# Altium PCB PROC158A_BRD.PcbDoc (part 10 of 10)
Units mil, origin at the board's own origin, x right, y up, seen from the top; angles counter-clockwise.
Board outline 3346.45 x 4921.26 mil, 8 copper layers (Top Layer, GND1, SIG1, PWR1, PWR2, SIG2, GND2, Bottom Layer), stack 54.534 mil thick; 718 components, 459 nets, 2307 pads, 1179 vias.
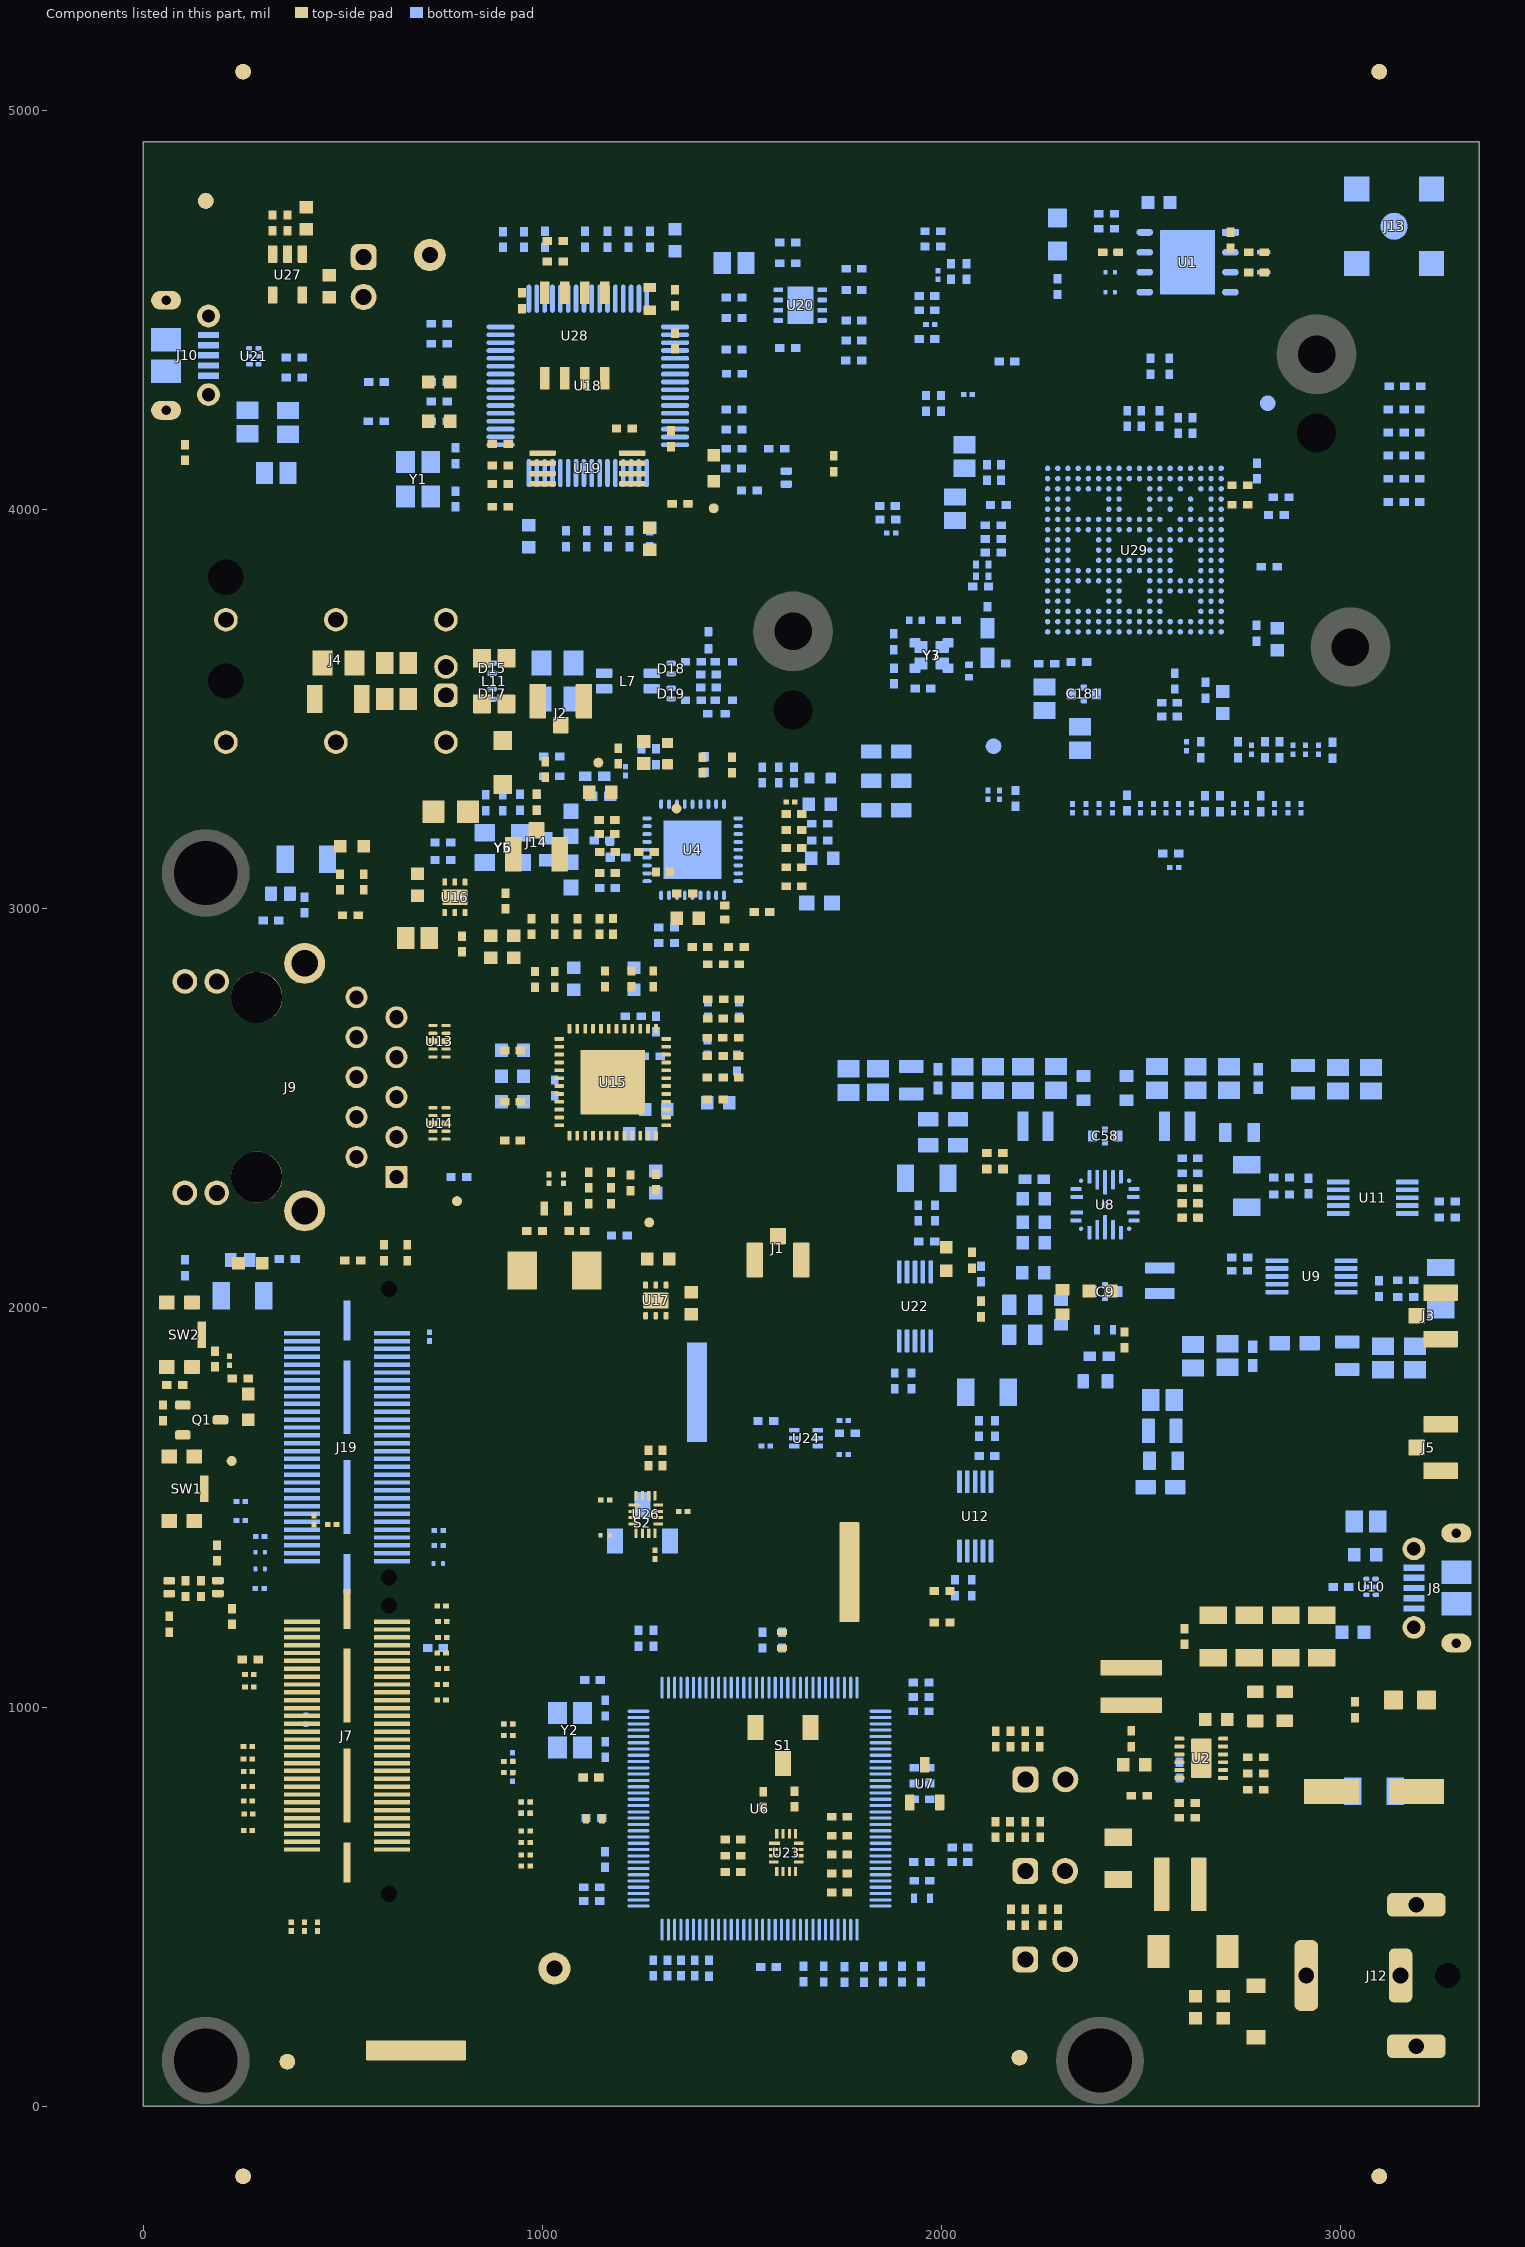
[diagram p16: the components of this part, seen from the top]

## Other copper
Top Layer:
  pour cut-out: 2380,1076 2380,1028.09 2570,1028.09 2570,1076
  pour cut-out: 473.41,3677.84 473.41,3464.33 806.94,3464.33 806.94,3677.84
  text ".Layer_Name" at 931.33,-846.68 h60
PWR1:
  pour cut-out: 2381,3395.5 2381,3394 2382.5,3392.5 2400,3392.5 2400,3395.5
  pour cut-out: 2290,3922.5 2290,3893 2289.5,3892.5 2285,3892.5 2285,3922.5
  text "PWR1" at 950,-848.19 h60
PWR2:
  text "PWR2" at 950,-848.19 h60
GND1:
  text "GND1" at 948.77,-848.19 h60
SIG1:
  text "SIG1" at 948.77,-848.19 h60
SIG2:
  text "SIG2" at 945.99,-848.19 h60
GND2:
  pour cut-out: 1914.4,3800 2011.73,3800 2022.06,3788.16 2137.22,3788.16 2137.22,3797 2032,3797 2019.99,3812 1911,3812 1840,3741 1840,3535 1868,3507 2135.9,3507 2213,3584.1 2213,3738.51 2200,3738.51 2200,3592.56 2125.41,3516.97 1871.56,3516.97 1850.89,3537.64 1850.89,3736.49
  text "GND4" at 950,-848.19 h60
Bottom Layer:
  pour cut-out: 2515,4285 2515,4228.32 2528.32,4228.32 2528.32,4284.68 2528,4285
  pour cut-out: 2820,3600 2820,3550 2885,3550 2885,3600
  pour cut-out: 2200,3432.31 2293.69,3432.31 2297,3429 2297,3417.76 2295.63,3416.39 2198.39,3416.39 2198,3416 2198,3430.31
  pour cut-out: 2187.04,3521.98 2187.04,3353.26 2189.19,3351.11 2195.52,3351.11 2200,3355.59 2200,3509.02
  pour cut-out: 2019,3876.75 2019,3812 2028,3812 2028,3876.75
  pour cut-out: 2102.11,3852.35 2027,3852.35 2027,3842.5 2102.11,3842.5
  pour cut-out: 2763,4105.53 2763,4140 2778,4155 2798,4155 2808,4145 2808,4128 2809,4127 2813,4127 2815,4129 2815,4147 2802,4160 2774,4160 2755.63,4141.63 2755.63,4106.34 2756.43,4105.53
  pour cut-out: 1980,3974.94 1980.06,3974.94 1990.06,3974.94 1990.06,3885.06 1990,3885 1980,3885 1980,3970
  pour cut-out: 1958,4205 2019,4205 2030,4216 2030,4287.4 2040,4287.4 2040,4211 2024,4195 1958,4195
  pour cut-out: 2480,4285 2480,4225 2485,4225 2485,4285
  pour cut-out: 2465,4298.89 2690,4298.89 2690,4285 2465,4285
  pour cut-out: 2065,3885 1980,3885 1980,3876.3 2065,3876.3
  pour cut-out: 2130,3880 2075,3880 2075,3875 2130,3875
  pour cut-out: 2125,3980 2075,3980 2075,3975 2125,3975
  pour cut-out: 2130,3915 2075,3915 2075,3905 2130,3905
  pour cut-out: 2130,3950 2075,3950 2075,3940 2130,3940
  pour cut-out: 2063.28,4000 2074.49,4000 2074.49,3860 2063.28,3860
  pour cut-out: 2846.42,4093 2846.42,3965.83 2901.83,3965.83 2914,3978 2914,4079 2900,4093
  pour cut-out: 2626.2,3525.25 2626.2,3430.34 2627.57,3428.96 2636.71,3428.96 2639.95,3432.2 2639.95,3521.51 2636.01,3525.45
  pour cut-out: 2545.45,3524.76 2640.36,3524.76 2641.73,3526.13 2641.73,3535.27 2638.5,3538.5 2549.18,3538.5 2545.25,3534.57
  pour cut-out: 1914.4,3800 2011.73,3800 2022.06,3788.16 2137.21,3788.16 2137.21,3797 2032,3797 2019.99,3812 1911,3812 1840,3741 1840,3535 1868,3507 2135.9,3507 2213,3584.1 2213,3738.51 2200,3738.51 2200,3592.56 2125.41,3516.97 1871.56,3516.97 1850.89,3537.64 1850.89,3736.49
  pour cut-out: 2145.5,2208.4 2168.7,2185.2 2218.8,2185.2 2220.7,2187.1 2220.7,2195.99 2219.08,2197.61 2187.58,2197.61 2187.58,2289.89 2183.77,2293.7 2145.5,2293.7
  pour cut-out: 707.45,3523.19 707.45,3450.86 779.27,3451.37 819.86,3410.78 1305.84,3410.78 1305.84,3248.87 1411.87,3248.87 1411.87,3388.93 1496.26,3388.93 1553.86,3446.54 1553.86,3589.84 1416.89,3726.81 811.62,3726.81 777.03,3692.22 705.86,3692.19 705.86,3621.04
  pour cut-out: 1736.49,2549.91 1733.39,2546.81 1716.41,2546.81 1716.41,2651.21 1807.09,2741.89 3026.11,2741.89 3125.11,2642.89 3125.11,2546.81 3109,2546.81 3109,2635 3017.86,2726.14 1811.02,2726.14 1736.49,2651.61
  pour cut-out: 2830,2520.13 2845,2520.13 2845,2741.89 2830,2741.89
  pour cut-out: 1955.56,2560 1975,2560 1975,2741.89 1955.56,2741.89
  pour cut-out: 2963.86,1870.81 2963.86,1751.81 3233.86,1751.81 3233.86,1871.81 3223.86,1871.81 3223.86,1761.81 2973.86,1761.81 2973.86,1870.81
  text ".Layer_Name" at 931.33,-846.68 h60

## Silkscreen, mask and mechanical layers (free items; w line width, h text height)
Top Overlay:
  circle w3.47: c1460.33,220.54 r10.78
  circle w3.47: c1460.33,220.54 r10.78
  lines w0.87: 1370.03,144.88 1465.54,192.2 ; 1465.54,192.2 1363.61,157.71 1465.54,192.2
  lines w1.73: 1459.13,189.43 1446.82,183.88 1459.13,189.43 ; 1459.13,189.43 1447.51,185.44 1459.13,189.43
  lines w3.47: 1446.82,184.4 1365.87,156.84 1446.82,184.4 ; 1446.82,184.4 1369.16,146.61 1446.82,184.4
  lines w6.93: 1378.52,154.07 1362.75,148.35 1378.52,154.07 ; 1378.52,154.07 1371.59,156.49 1378.52,154.07 ; 1201.71,221.67 1211.24,226.53 1201.71,221.67 ; 1368.81,152.51 1419.43,172.96 1368.81,152.51
  lines w15.6: 1136.18,163.08 1121.62,146.96 1136.18,163.08 ; 1136.18,163.08 1145.72,172.79 ; 1136.18,163.08 1145.72,172.79 ; 1145.72,172.79 1154.38,181.11 ; 1145.72,172.79 1154.38,181.11 ; 1154.38,181.11 1158.89,185.44 ; 1154.38,181.11 1158.89,185.44 ; 1158.89,185.44 1169.29,193.76 ; 1158.89,185.44 1169.29,193.76 ; 1169.29,193.76 1179,201.74 ; 1169.29,193.76 1179,201.74 ; 1179,201.74 1182.81,204.34 ; 1179,201.74 1182.81,204.34 ; 1182.81,204.34 1187.32,207.11 ; 1182.81,204.34 1187.32,207.11 ; 1187.32,207.11 1194.43,211.62 1187.32,207.11 ; 1203.44,217.86 1185.93,206.94 1203.44,217.86 ; 1203.44,217.86 1186.63,207.11 1203.44,217.86 ; 1215.92,164.64 ccw(c1225.5,157.35) 1233.08,148 ; 1215.92,164.64 ccw(c1225.5,157.35) 1233.08,148 ; 1215.92,164.64 1249.72,209.02 ; 1215.92,164.64 1249.72,209.02 ; 1223.38,227.57 1211.93,222.02 1223.38,227.57 ; 1223.38,227.57 1232.22,231.21 ; 1223.38,227.57 1232.22,231.21 ; 1232.22,231.21 cw(c1240.04,214.54) 1249.2,230.51 ; 1232.22,231.21 cw(c1240.04,214.54) 1249.2,230.51 ; 1233.08,148 cw(c1482.55,-286.74) 1335.88,192.55 ; 1233.08,148 cw(c1482.55,-286.74) 1335.88,192.55 ; 1249.2,230.51 cw(c1245.39,223.86) 1252.84,225.66 ; 1249.2,230.51 cw(c1245.39,223.86) 1252.84,225.66 ; 1249.72,209.02 ccw(c1232.76,220.81) 1252.84,225.66 ; 1249.72,209.02 ccw(c1232.76,220.81) 1252.84,225.66 ; 1335.88,192.55 cw(c1337.59,180.03) 1349.92,182.84 ; 1335.88,192.55 cw(c1337.59,180.03) 1349.92,182.84 ; 1349.92,182.84 cw(c1301.06,171.67) 1350.44,163.08 ; 1349.92,182.84 cw(c1301.06,171.67) 1350.44,163.08 ; 1350.44,163.08 ccw(c1361.72,161.12) 1365.35,150.25 cw(c1361.72,161.12) 1350.44,163.08 ; 1191.65,209.71 1198.07,214.05 1191.65,209.71 ; 1194.95,212.49 1207.25,219.25 1194.95,212.49
  text "VPP_1P7" at 486.81,4734.41 h40
  text "GND" at 677.97,4536.87 h40
  text "FTDI_NSUSP" at 1216.64,4421.77 h35 r90
  text "FTDI_USB" at 304.63,4247.11 h60 r90
  text "WRMRST" at 1379.79,4042.78 h35 r90
  text "OSC_CLKTOP" at 1161,3511 h40
  text "ETH_LED" at 284.18,3199.66 h50
  text "RJ45_VCC" at 716,2297 h40
  text "ETH_CLKOUT" at 1229.19,2239.08 h40
  text "NERR_OUT" at 1918.89,2202.92 h40
  text "ETH_LED" at 187.13,2163.9 h40
  text "1V0" at 1557.94,2009.54 h40
  text "TRIG_GPIO" at 193.17,1954.21 h40
  text "For evaluation only; not FCC" at 1389.72,1867.72 h60
  text "approved for resale." at 1499,1808 h60
  text "CAUTION HOT SURFACE" at 2511.68,1786.02 h25
  text "NRST" at 336.99,1717.64 h40 r90
  text "AWR2544 LOP EVM" at 1876.17,1621.98 h60
  text "'.PRJ_Number'" at 1966.14,1502 h60
  text "NRST" at 172.83,1476.13 h40
  text "GND" at 1822,1395 h40
  text "REV. A" at 2151.08,1372 h60
  text "DEBUG_CONN" at 324.77,1369.35 h60
  text "XDS_USB" at 3092.07,1193.92 h50 r90
  text "VBAT" at 3175.12,1078.73 h40
  text "JTAG_MUX" at 1515,1062 h35
  text "MIPI" at 1640.9,1013.39 h35
  text "XDS" at 1501,1013 h35
  text "SOP0" at 2044,760 h40
  text "SOP1" at 2044,536 h40
  text "GND" at 1107,336 h40
  text "SOP2" at 2044,308 h40
  text "R" at 1456.35,216.03 h10.4
  text "R" at 1456.35,216.03 h10.4
  text "GND" at 639.24,192.36 h40
  text "MISTRAL" at 1113.47,63.58 h80
  text ".Layer_Name" at 931.33,-846.68 h60
Bottom Overlay:
  circle w6: c657.29,3975.77 r13.43
  lines w10: 2716.12,972.53 2716.12,1122.53 ; 2028.24,972.53 2920.89,972.53 2920.89,1122.53 2028.24,1122.53 2028.24,972.53 ; 2309.76,1171.06 2922.67,1171.06 2922.67,1272.53 2309.76,1272.53 2309.76,1171.06
  text "FTDI_USB" at 292,4644 h60
  text "MSS_GPIO2" at 2205,4567 h40 r270
  text "GND" at 786.99,4521.46 h60
  text "CLKP_SMA" at 3259.5,4457.21 h40
  text "AUTO_ETH_JACK" at 536.19,3243.96 h60
  text "ETH_JACK" at 731.64,2386.93 h60 r270
  text "1V0" at 1840,2239 h30
  text "1V8" at 2747,2179 h40
  text "1V2" at 3289.9,2143.64 h40
  text "1V0_FILT" at 2061.93,2142 h25 r270
  text "GND" at 1513.05,1827.27 h40
  text "3V3" at 2039,1714 h40
  text "MIPI_CONN" at 326.39,1710.87 h60
  text "XDS_USB" at 3269.19,1544.94 h50
  text "FTDI_SPI" at 1202,1324 h40
  text "DBG_SPI" at 1441,1322 h40
  text "SPI_MUX" at 1332,1248 h40
  text "ASSY REV:" at 2900.08,1200.83 h60
  text "SL#" at 2896.12,1014.47 h100
  text "SOP3" at 2134.25,673.91 h35
  text "SOP4" at 1967,400 h35
  text "12V, >2.5A" at 2855.61,304.31 h60
  text "FY22-23/02406000101" at 1228,119 h80
  text ".Layer_Name" at 931.33,-846.68 h60
Top Paste:
  text ".Layer_Name" at 931.33,-846.68 h60
Bottom Paste:
  text ".Layer_Name" at 931.33,-846.68 h60
Top Solder:
  text ".Layer_Name" at 931.33,-846.68 h60
  text ".Layer_Name" at 931.33,-846.68 h60
Bottom Solder:
  text ".Layer_Name" at 931.33,-846.68 h60
Drill Guide:
  text ".Layer_Name" at 931.33,-846.68 h60
M1 Board Outline:
  lines w2: 0,0 0,4921.25 ; 0,0 0,-275.59 3346.45,-275.59 3346.45,0 ; 0,0 3346.45,0 ; 0,4921.25 0,5196.85 3346.45,5196.85 3346.45,4921.26 ; 0,4921.26 3346.45,4921.26 ; 3346.45,0 3346.45,4921.25
  text ".Layer_Name" at 469.25,-764.18 h30
M2 Board Dimensions:
  text ".Layer_Name" at 1011.76,-766.86 h30
M3 3D STEP Top:
  text ".Layer_Name" at 931.33,-846.68 h60
M4 3D STEP Bottom:
  text ".Layer_Name" at 931.33,-846.68 h60
M5 Assembly Top:
  lines w4: 850,2380 970,2380 995,2355 ; 975,2355 995,2355 ; 995,2375 995,2355 ; 1560,2750 1540,2770 ; 1560,2790 1540,2770 ; 1660,2770 1540,2770 ; 660,2270 740,2270 740,2160 850,2160 850,2400 660,2400 660,2270 ; 1660,2583.76 1910,2583.76 1910,2850 1681.55,2850 1660,2828.45 1660,2583.76
  lines w10: 62.33,-918.36 6662.33,-918.36 ; 62.33,-715.02 6664.33,-715.02 ; 62.33,-511.69 62.33,-1121.69 4067.33,-1121.69 6664.33,-1121.69 6664.33,-511.69 62.83,-511.69 62.83,-1121.69 1638.33,-1121.69 ; 2527.33,-1121.69 2527.33,-511.69 ; 3794.33,-715.02 3794.33,-511.69 ; 4634.33,-715.02 4634.33,-511.69 ; 5256.33,-1128.19 5256.33,-925.36
  text "COMPONENTS MARKED 'DNP' SHOULD NOT BE POPULATED." at 3558.2,-220.46 h60
  text "ASSEMBLY VARIANT:" at 3557.7,-335.96 h60
  text ".VariantName" at 4593.7,-335.96 h60
  text "PCB VIEWED FROM TOP SIDE" at 125.83,-643.86 h60
  text "BOARD #:" at 2602.33,-643.86 h60
  text ".PRJ_Number" at 3147.83,-643.86 h60
  text "REV:" at 3992.33,-643.86 h60
  text ".PCB_Rev" at 4283.83,-643.86 h60
  text "SVN REV:" at 4830.33,-643.86 h60
  text ".VersionControl_RevNumber" at 5336.33,-643.86 h60
  text "TID #:" at 2602.33,-847.19 h60
  text ".TID" at 3147.83,-847.19 h60
  text "PLOT NAME =" at 125.83,-1052.52 h60
  text ".plot_File_Name" at 931.33,-1052.52 h60
  text "GENERATED    :" at 2604.33,-1052.52 h60
  text ".Print_Date" at 3473.83,-1052.52 h60
  text ".Print_Time" at 4202.83,-1052.52 h60
  text "TEXAS INSTRUMENTS" at 5467.33,-1052.52 h60
M6 Assembly Bottom:
  lines w4: 1209,3074 1220,3092 ; 1231,3074 1220,3092 ; 2191,4002 2191,3983 ; 2210,3983 2191,3983 ; 985,2894.76 1035.24,2945 1185,2945 1220,2980 1220,3092 ; 985,2894.76 754,2894.76 754,2747 985,2747 985,2894.76 ; 2191,3983 2212,4004 2212,4024 2212,4147 2265,4200 ; 2265,4200 2265,4370 2395,4370 2395,4200 2265,4200
  lines w10: 61.83,-715.52 6663.83,-715.52 ; 63.83,-918.86 6663.83,-918.86 ; 1469.83,-1128.69 1469.83,-925.86 ; 2091.83,-715.52 2091.83,-512.19 ; 2931.83,-715.52 2931.83,-512.19 ; 4198.83,-1122.19 4198.83,-512.19 ; 5087.83,-1122.19 6663.33,-1122.19 6663.33,-512.19 61.83,-512.19 61.83,-1122.19 2658.83,-1122.19 6663.83,-1122.19 6663.83,-512.19
  text "COMPONENTS MARKED 'DNP' SHOULD NOT BE POPULATED." at 6456.33,-306.19 h60
  text ".VariantName" at 5412.33,-422.19 h60
  text "ASSEMBLY VARIANT:" at 6451.33,-422.19 h60
  text ".VersionControl_RevNumber" at 1389.83,-644.36 h60
  text "SVN REV:" at 1895.83,-644.36 h60
  text ".PCB_Rev" at 2442.33,-644.36 h60
  text "REV:" at 2733.83,-644.36 h60
  text ".PRJ_Number" at 3578.33,-644.36 h60
  text "BOARD #:" at 4123.83,-644.36 h60
  text "PCB VIEWED FROM BOTTOM SIDE" at 6600.33,-644.36 h60
  text ".TID" at 3578.33,-847.69 h60
  text "TID #:" at 4123.83,-847.69 h60
  text "TEXAS INSTRUMENTS" at 1258.83,-1053.02 h60
  text ".Print_Time" at 2523.33,-1053.02 h60
  text ".Print_Date" at 3252.33,-1053.02 h60
  text "GENERATED    :" at 4121.83,-1053.02 h60
  text ".plot_File_Name" at 5794.83,-1053.02 h60
  text "PLOT NAME =" at 6600.33,-1053.02 h60
M9 Title Sheet:
  drawing of 57 lines, arcs and shapes, not listed
  text "1" at 694.17,8048.31 h70
  text "2" at 3189.83,8048.31 h70
  text "3" at 5679.17,8048.31 h70
  text "4" at 8185.84,8048.31 h70
  text "5" at 10684.83,8048.31 h70
  text "6" at 13189.83,8048.31 h70
  text "A" at -462.17,6905.31 h70
  text "A" at 14337.83,6905.31 h70
  text "B" at -462.17,4525.31 h70
  text "B" at 14337.83,4525.31 h70
  text "C" at -462.17,2150.31 h70
  text "C" at 14337.83,2150.31 h70
  text "PROJECT TITLE:" at 11297.83,289.31 h45
  text ".PRJ_Title" at 11347.83,155.98 h70
  text "DESIGNED FOR:" at 11297.83,-11.69 h45
  text ".PRJ_Customer" at 11347.83,-151.69 h70
  text "D" at -462.17,-219.69 h70
  text "D" at 14337.83,-219.69 h70
  text "FILE NAME:" at 11297.83,-311.69 h45
  text ".PCB_File_Name_No_Path" at 11347.83,-431.69 h70
  text "Texas Instruments (TI) and/or its licensors do not warrant the accuracy or completeness of this specification" at 6328.33,-593.53 h45
  text "ENGINEER:" at 11297.83,-601.69 h45
  text "LAYOUT BY:" at 12802.83,-601.69 h45
  text "or any information contained therein. TI and/or its licensors do not warrant that this design will meet" at 6283.35,-706.19 h45
  text ".PRJ_Engineer" at 11347.83,-756.68 h70
  text ".PCB_Layout" at 12853.33,-756.68 h70
  text "the specifications, will be suitable for your application or fit for any particular purpose, or will operate in" at 6283.35,-818.86 h45
  text ".Layer_Name" at 476.17,-895.69 h30
  text "ALTIUM DESIGNER VERSION:" at 12802.83,-911.69 h45
  text "an implementation. TI and/or its licensors do not warrant that the design is production worthy. You should" at 6283.35,-931.52 h45
  text "completely validate and test your design implementation to confirm the system functionality for your application." at 6328.33,-1044.19 h45
  text ".print_Scale" at 11347.83,-1045.02 h70
  text ".Application_BuildNumber" at 12853.33,-1045.02 h70
  text "1" at 694.17,-1251.69 h70
  text "2" at 3189.83,-1251.69 h70
  text "3" at 5679.17,-1251.69 h70
  text "4" at 8185.84,-1251.69 h70
  text "5" at 10684.83,-1251.69 h70
  text "6" at 13189.83,-1251.69 h70
M10 Fab Notes:
  drawing of 266 lines, arcs and shapes, not listed
  text "DESIGN INFORMATION" at 12336.35,6367.99 h60
  text "MIN. TRACK WIDTH:" at 11691.79,6235.86 h60
  text "4" at 12788.03,6235.86 h60
  text "MIL" at 12942.79,6235.86 h60
  text "3.6" at 12734.95,6114.9 h60
  text "MIN. CLEARANCE:" at 11691.79,6111.73 h60
  text "MIL" at 12940,6111.81 h60
  text "16" at 12761.35,5999.61 h60
  text "MIN. VIA PAD SIZE:" at 11691.79,5987.61 h60
  text "MIL" at 12942.79,5987.61 h60
  text "MINIMUM ANNULAR RING" at 11327.35,5859.09 h60
  text "0.114mm (4.5MIL)" at 12386.79,5857.71 h60
  text "EXTERNAL" at 13140,5851.81 h60
  text "PER" at 11562.56,5739.36 h60
  text "IPC-D-275 CLASS 2 LEVEL C" at 11782.56,5739.36 h60
  text "MIL, HOLES" at 13270.79,5638.88 h60
  text "+/-" at 12878.33,5630.29 h60
  text "+/-" at 13732.33,5630.29 h60
  text "REGISTRATION TOLERANCES:" at 11362.56,5629.23 h60
  text "METAL" at 12562.33,5629.23 h60
  text "2" at 13138.53,5629.23 h60
  text "3" at 13971.53,5629.23 h60
  text "MIL" at 14087.79,5629.23 h60
  text "HOLE SIZE TOLERANCE (UNLESS OTHERWISE SPECIFIED):" at 11362.56,5530.91 h60
  text "+/-" at 13732.33,5528.04 h60
  text "3" at 13971.53,5526.98 h60
  text "MIL" at 14087.79,5526.98 h60
  text "MATERIAL:" at 11287.79,5389.33 h60
  text "X" at 12133.34,5260.81 h60
  text "FR-4 High Tg" at 12274.23,5260.81 h60
  text "FR-408" at 11708.79,5248.3 h60
  text "OTHER" at 13196.79,5248.3 h60
  text "64 MIL (1.63mm) +/-10%" at 12028.89,5105.27 h60
  text "X" at 13199.4,5104.68 h60
  text ".Total_Thickness" at 13620.02,5098.36 h50
  text "+/-10%" at 13940.35,5098.64 h50
  text "THICKNESS:" at 11362.56,5097.05 h60
  text "OTHER" at 13313.79,5097.05 h60
  text "TOLERANCE:" at 11362.56,4958.73 h60
  text "X" at 12210.8,4958.73 h60
  text "ANSI IPC-6012 TYPE 3 CLASS 2" at 12388.81,4958.73 h60
  text "OTHER +/-" at 12388.79,4814.54 h60
  text "BOW & TWIST:" at 11362.56,4669.36 h60
  text "X" at 12210.8,4669.36 h60
  text "ANSI IPC-6012 TYPE 3 CLASS 2" at 12388.81,4669.36 h60
  text "OTHER +/-" at 12388.79,4522.66 h60
  text "DRILLING:" at 11287.79,4392.04 h60
  text "NC_DRILL FILES" at 13048.79,4286.85 h60
  text "REFERENCE:" at 11362.56,4282.91 h60
  text "X" at 12019.8,4282.82 h60
  text "AS SHOWN" at 12197.79,4282.91 h60
  text "X" at 12920.8,4282.91 h60
  text "OTHER" at 13346.79,4140.66 h60
  text "PTH COPPER THICKNESS:" at 11362.24,4137.13 h60
  text "X" at 12501.47,4137.13 h60
  text "20-30 um" at 12629.47,4137.13 h60
  text "BOARD FINISH:" at 11287.79,3989.54 h60
  text "SILKSCREEN:" at 11443.01,3879.41 h60
  text "X" at 12400.8,3879.41 h60
  text "TOP" at 12517.79,3879.41 h60
  text "X" at 12910.8,3879.41 h60
  text "BOTTOM" at 13028.79,3879.41 h60
  text "SILKSCREEN COLOR:" at 11443.01,3724.22 h60
  text "X" at 12399.8,3724.22 h60
  text "WHITE" at 12517.79,3724.22 h60
  text "OTHER" at 13028.79,3724.22 h60
  text "RED" at 13755.79,3588.91 h60
  text "X" at 13124.17,3583.09 h60
  text "GREEN" at 12648.79,3580.77 h60
  text "OTHER" at 13266.79,3580.77 h60
  text "SOLDER RESIST COLOR:" at 11443.01,3573.91 h60
  text "NOTES : UNLESS OTHERWISE SPECIFIED." at 5662.68,3552.61 h60
  text "X" at 12530.8,3426.52 h60
  text "MATTE" at 12648.79,3426.52 h60
  text "SEMI-GLOSS" at 13266.33,3425.88 h60
  text "1. FABRICATE PER IPC-6012A CLASS 2." at 5809.95,3404.61 h60
  text "2. FOR IMPEDANCE DETAILS REFER STACKUP & IMPEDANCE TABLE." at 5809.95,3284.61 h60
  text "IMMERSION GOLD (ENIG)" at 12348.79,3253.75 h60
  text "ENEPIG" at 13686.33,3246.53 h60
  text "SURFACE FINISH:" at 11287.79,3245.53 h60
  text "X" at 12169.87,3245.53 h60
  text "3. PRINTED WIRING BOARD SHALL COMPLY WITH REQUIREMENTS OF ANSI/J-STD-003." at 5809.95,3164.61 h60
  text "IMM. TIN/SILVER OR EQUIV" at 11617.33,3108.21 h60
  text "OTHER" at 13048.79,3104.28 h60
  text "4. SURFACE FINISH: ENIG" at 5809.95,3044.61 h60
  text "ARRAY/PANEL:" at 11287.79,2948.9 h60
  text "CUT AND TRIM PER M1 BOARD OUTLINE" at 12348.79,2940.68 h60
  text "5. SOLDERMASK ON BOTH SIDES OF THE BOARD SHALL BE LPI, COLOR RED." at 5809.95,2924.61 h60
  text "X" at 13035,2806.81 h60
  text "6. SILK SCREEN LEGEND TO BE APPLIED PER LAYER STACKUP USING WHITE" at 5809.95,2804.61 h60
  text "N.C. ROUTE" at 12348.79,2804.71 h60
  text "V. SCORE" at 13214.79,2804.71 h60
  text "NON-CONDUCTIVE EPOXY INK." at 5932.05,2704.61 h60
  text "CERTIFICATION:" at 11287.79,2675.58 h60
  text "MATERIALS AND WORKMANSHIP FOR ALL PCBS" at 12012.79,2675.58 h60
  text "7. THIS PRINTED WIRING BOARD IS DESIGNED WITH A MINIMUM CONDUCTOR" at 5809.95,2604.61 h60
  text "TO MEET OR EXCEED THE REQUIREMENTS OF:" at 12012.79,2581.52 h60
  text "WIDTH AND SPACING OF 4 MIL &  3.6 MILS." at 5932.05,2504.61 h60
  text "X" at 11650.3,2452.89 h60
  text "ANSI IPC-A-600F CLASS ->" at 11778.29,2452.89 h60
  text "X" at 13426.3,2452.89 h60
  text "2" at 13536.29,2452.89 h60
  text "1" at 13221.29,2451.39 h60
  text "3" at 13890.29,2451.39 h60
  text "8. ALL VIAS ARE TENTED ON BOTH SIDES UNLESS SOLDERMASK OPENED IN GERBER." at 5809.95,2404.61 h60
  text "9. ALL VIAS SHOULD BE FILLED WITH NON CONDUCTIVE EPOXY AND SURFACE SHOULD BE FLAT" at 5809.95,2304.61 h60
  text "X" at 12462.3,2305.21 h60
  text "RoHS" at 12590.29,2305.21 h60
  text "OTHER" at 13234.7,2305.21 h60
  text "PER ORDER" at 13631.75,2305.21 h60
  text "10. VENDOR SHOULD FOLLOW ROHS COMPLIANT PROCESS AND Pb FREE FOR MANUFACTURING" at 5770.06,2163.15 h60
  text "ALL BOARDS MUST MEET OR EXCEED UL94-V0 REQUIREMENTS." at 11315.33,2151.38 h60
  text "11. MANUFACTURER'S IDENTIFICATION, DATECODE LETTER SHALL BE SILKSCREENED ON SOLDER SIDE" at 5770.06,2043.15 h60
  text "PCB MUST BEAR THE UL94V-0 UL REGISTERED MATERIAL ID NUMBER" at 11315.33,2035.32 h60
  text "OF THE BOARD." at 5932.16,1923.15 h60
  text "ADDITIONAL REQUIREMENTS:" at 11287.79,1865.89 h60
  text "12. BOARD DIMENSIONS ARE IN MM." at 5768.49,1822.38 h60
  text "MICROSECTION:" at 11362.56,1758.76 h60
  text "YES" at 12268.29,1758.76 h60
  text "13. BOW AND TWIST SHALL NOT EXCEED 0.7% OF LONGEST SIDE" at 5768.49,1682.38 h60
  text "REQUIRED" at 13129.79,1614.43 h60
  text "BARE BOARD ELEC. TEST:" at 11362.56,1611.58 h60
  text "NONE" at 12668.29,1611.58 h60
  text "X" at 13011.8,1611.58 h60
  text "PER ORDER" at 13721.79,1611.58 h60
  text "14. TEAR DROPS SHALL BE ADDED ON INTERNAL AND EXTERNAL LAYER FOR ALL THE VIA'S AND THROUGH HOLE PADS." at 5768.06,1547.64 h60
  text "X" at 11414.11,1464.29 h60
  text "8 & 10 MIL VIAS REQUIRE NON-CONDUCTIVE FILL AND PLANARIZE" at 11551.06,1396.93 h59
  text "15. PCB Material must meet or exceed UL94V-0 requirements." at 5768.49,1392.38 h60
  text "XX MIL VIAS REQUIRE CONDUCTIVE FILL AND PLANARIZE" at 11538.71,1302.65 h60
  text "PCB must bear the UL94V-0 registered material ID number." at 5930.59,1252.38 h60
  text "R 0.20(mm)" at 4553,1237 h60
  text "BOARD IMPEDANCE SHALL BE FOLLOWED AS PER THE" at 11560,1168.81 h58
  text "X" at 11421.11,1137.51 h60
  text "R 0.30(mm)" at 4553,1136 h60
  text "16. LAYER TO LAYER REGISTRATION SHALL BE WITHIN +/-2 MIL" at 5768.49,1112.38 h60
  text "IMPEDANCE SPECIFICATION TABLE." at 11552,1070.81 h58
  text "17. BOARD SHALL HAVE THE CUTOUTS AS INDICATED." at 5786.38,982.13 h60
  text "18. THE DETAIL \"A\" CUTOUT SHALL FOLLOW BELOW INSTRUCTIONS." at 5785.11,814.22 h60
  text "1.13(mm)" at 3690.76,667 h60 r90
  text "0.50(mm)" at 4641,667 h60 r90
  text "1.78(mm)" at 4403,546 h60
  text "A) INDICATED DIMENSIONS ON DETAIL \"A\" IS FINISHED AFTER PLATING. TOLERANCE AFTER PLATING SHALL BE WITHIN +/- 0.05MM" at 5940,460 h60
  text "0.27(mm)" at 4403,403 h60
  text "19. INDICATED CUTOUT DETAILS ARE MEASURED AFTER PLATING AND DATA SHALL BE PROVIDED ALONG WITH THE COC" at 5788.56,331.52 h60
  text "20. ALL UNCONNECTED VIA'S SHALL BE SUPPRESSED." at 5788.56,189.35 h60
  text "CUTOUT DETAIL - \"A\"" at 3481.18,179.87 h100
  text ".Layer_Name" at 931.33,-846.68 h60
M11 Gerber Information:
  lines w10: -337.67,-918.36 6262.33,-918.36 ; -337.67,-715.02 6264.33,-715.02 ; -337.67,-511.69 -337.67,-1121.69 3667.33,-1121.69 6264.33,-1121.69 6264.33,-511.69 -337.17,-511.69 -337.17,-1121.69 1238.33,-1121.69 ; 2127.33,-1121.69 2127.33,-511.69 ; 3394.33,-715.02 3394.33,-511.69 ; 4234.33,-715.02 4234.33,-511.69 ; 4856.33,-1128.19 4856.33,-925.36
  text "ALL ARTWORK VIEWED FROM TOP SIDE" at -274.17,-643.86 h60
  text "BOARD #:" at 2202.33,-643.86 h60
  text ".PRJ_Number" at 2747.83,-643.86 h60
  text "REV:" at 3592.33,-643.86 h60
  text ".PCB_Rev" at 3883.83,-643.86 h60
  text "SVN REV:" at 4430.33,-643.86 h60
  text ".VersionControl_RevNumber" at 4936.33,-643.86 h60
  text "LAYER NAME =" at -274.17,-846.68 h60
  text "TID #:" at 2202.33,-847.19 h60
  text ".TID" at 2747.83,-847.19 h60
  text "PLOT NAME =" at -274.17,-1052.52 h60
  text ".plot_File_Name" at 531.33,-1052.52 h60
  text "GENERATED    :" at 2204.33,-1052.52 h60
  text ".Print_Date" at 3073.83,-1052.52 h60
  text ".Print_Time" at 3802.83,-1052.52 h60
  text "TEXAS INSTRUMENTS" at 5067.33,-1052.52 h60
M12 Stackup:
  drawing of 173 lines, arcs and shapes, not listed
  text "2" at -78.92,7702.95 h100
  text "IMPEDANCE SPECIFICATIONS" at 100.06,7682.61 h100
  text "IMPEDANCE SPECIFICATIONS" at 100.06,7682.61 h100
  text "SL#" at -34.94,7332.61 h100
  text "SL#" at -34.94,7332.61 h100
  text "TYPE" at 1350.06,7332.61 h100
  text "TYPE" at 1350.06,7332.61 h100
  text "LAYER" at 2810.06,7332.61 h100
  text "LAYER" at 2810.06,7332.61 h100
  text "TRACEWIDTH(Mils)" at 3645.06,7332.61 h100
  text "TRACEWIDTH(Mils)" at 3645.06,7332.61 h100
  text "SPACING(Mils)" at 5290.06,7332.61 h100
  text "SPACING(Mils)" at 5290.06,7332.61 h100
  text "IMPEDANCE(Ohms)" at 6605.06,7332.61 h100
  text "IMPEDANCE(Ohms)" at 6605.06,7332.61 h100
  text "REF LAYER" at 8225.06,7332.61 h100
  text "REF LAYER" at 8225.06,7332.61 h100
  text "---" at 5674.08,7116.95 h100
  text "L1" at 2934.66,7115.95 h100
  text "L02" at 8387.07,7115.95 h100
  text "8" at 4122.05,7106.61 h100
  text "50" at 7122.05,7103.61 h100
  text "01" at 9.08,7099.95 h100
  text "MICROSTRIP" at 352.65,7092.02 h100
  text "4.55" at 5694.08,6937.95 h100
  text "EDGE COUPLED MICROSTRIP" at 354.16,6931.75 h100
  text "5.65" at 4019.93,6931.61 h100
  text "L1" at 2934.66,6930.95 h100
  text "90" at 7122.05,6928.61 h100
  text "L02" at 8387.07,6928.95 h100
  text "02" at 5.26,6920.94 h100
  text "L02" at 8387.07,6758.95 h100
  text "EDGE COUPLED MICROSTRIP" at 354.16,6757.38 h100
  text "4.8" at 4061.83,6756.61 h100
  text "L1" at 2934.66,6755.95 h100
  text "100" at 7085.39,6753.61 h100
  text "5.4" at 5736.21,6747.95 h100
  text "03" at 5.26,6745.94 h100
  text "EDGE COUPLED STRIPLINE" at 353.82,6585.66 h100
  text "L02/L04,L05/L07" at 7949.78,6585.81 h100
  text "L3, L6" at 2782.08,6582.39 h100
  text "7.2" at 5738.59,6573.47 h100
  text "04" at 5.26,6570.94 h100
  text "4.8" at 4061.83,6571.08 h100
  text "100" at 7085.39,6570.74 h100
  text "STRIPLINE" at 351.56,6410.44 h100
  text "L3, L6" at 2782.08,6410.12 h100
  text "6" at 4124.43,6404.95 h100
  text "50" at 7122.05,6403.61 h100
  text "L02/L04,L05,L07" at 7970.73,6403.61 h100
  text "---" at 5674.08,6401.35 h100
  text "05" at 5.26,6395.94 h100
  text "---" at 5674.08,6238.46 h100
  text "L8" at 2913.24,6237.46 h100
  text "8" at 4122.05,6237.36 h100
  text "L07" at 8387.07,6237.46 h100
  text "50" at 7122.05,6225.13 h100
  text "06" at 5.26,6220.94 h100
  text "MICROSTRIP" at 337.06,6213.53 h100
  text "4.55" at 5694.08,6062.95 h100
  text "EDGE COUPLED MICROSTRIP" at 354.16,6056.75 h100
  text "5.65" at 4019.93,6056.61 h100
  text "L8" at 2913.24,6055.95 h100
  text "90" at 7122.05,6053.61 h100
  text "L07" at 8387.07,6053.95 h100
  text "07" at 15.07,6048.78 h100
  text "L07" at 8387.07,5883.95 h100
  text "EDGE COUPLED MICROSTRIP" at 354.16,5882.38 h100
  text "4.8" at 4061.83,5881.61 h100
  text "L8" at 2913.24,5880.95 h100
  text "100" at 7085.39,5878.61 h100
  text "08" at 9.08,5874.95 h100
  text "5.4" at 5736.21,5872.95 h100
  text "6.2" at 5741.21,5712.95 h100
  text "EDGE COUPLED STRIPLINE" at 354.16,5707.38 h100
  text "5.8" at 4061.83,5706.61 h100
  text "L6" at 2915.62,5705.95 h100
  text "90" at 7122.05,5703.61 h100
  text "L07" at 8387.07,5703.95 h100
  text "09" at 9.08,5699.95 h100
  text "THIS IS AN IMPEDANCE CONTROLLED BOARD." at -92.72,5531.85 h75
  text "2" at 4558.52,5399.06 h100
  text "LAYER STACKUP" at 4722.51,5384.72 h100
  text "LAYER STACKUP" at 4722.51,5384.72 h100
  text "NOTE :" at -71.11,5323.9 h75
  text "Layer" at 4555.71,5256.72 h35.86
  text "Name" at 4808.72,5256.72 h35.86
  text "Material" at 5372.37,5256.72 h35.86
  text "Thickness" at 5894.2,5256.72 h35.86
  text "Constant" at 6290.58,5256.72 h35.86
  text "Gerber" at 6639.17,5256.72 h35.86
  text "Top Overlay" at 4808.72,5185.01 h35.86
  text "GTO" at 6639.17,5185.01 h35.86
  text "EXTERNAL LAYER CU THICKNESSES ARE FINISHED THICKNESS AFTER PLATING." at -71.11,5164.75 h75
  text "Top Solder" at 4808.72,5113.3 h35.86
  text "Solder Resist" at 5372.37,5113.3 h35.86
  text "1.00mil" at 5894.2,5113.3 h35.86
  text "3.5" at 6290.58,5113.3 h35.86
  text "GTS" at 6639.17,5113.3 h35.86
  text "1" at 4555.71,5041.59 h35.86
  text "Top Layer" at 4808.72,5041.59 h35.86
  text "1.85mil" at 5894.2,5041.59 h35.86
  text "GTL" at 6639.17,5041.59 h35.86
  text "Dielectric 1" at 4808.72,4969.88 h35.86
  text "FR-4 High Tg" at 5372.37,4969.88 h35.86
  text "4.40mil" at 5894.2,4969.88 h35.86
  text "3.54" at 6290.58,4969.88 h35.86
  text "2" at 4555.71,4898.17 h35.86
  text "GND1" at 4808.72,4898.17 h35.86
  text "1.26mil" at 5894.2,4898.17 h35.86
  text "G1" at 6639.17,4898.17 h35.86
  text "Dielectric 2" at 4808.72,4826.46 h35.86
  text "FR-4 High Tg" at 5372.37,4826.46 h35.86
  text "5.00mil" at 5894.2,4826.46 h35.86
  text "3.88" at 6290.58,4826.46 h35.86
  text "3" at 4555.71,4754.75 h35.86
  text "SIG1" at 4808.72,4754.75 h35.86
  text "0.69mil" at 5894.2,4754.75 h35.86
  text "G2" at 6639.17,4754.75 h35.86
  text "Dielectric 3" at 4808.72,4683.04 h35.86
  text "FR-4 High Tg" at 5372.37,4683.04 h35.86
  text "10.31mil" at 5894.2,4683.04 h35.86
  text "3.86" at 6290.58,4683.04 h35.86
  text "4" at 4555.71,4611.33 h35.86
  text "PWR1" at 4808.72,4611.33 h35.86
  text "1.26mil" at 5894.2,4611.33 h35.86
  text "G3" at 6639.17,4611.33 h35.86
  text "Dielectric 4" at 4808.72,4539.62 h35.86
  text "FR-4 High Tg" at 5372.37,4539.62 h35.86
  text "5.00mil" at 5894.2,4539.62 h35.86
  text "3.88" at 6290.58,4539.62 h35.86
  text "5" at 4555.71,4467.91 h35.86
  text "PWR2" at 4808.72,4467.91 h35.86
  text "1.26mil" at 5894.2,4467.91 h35.86
  text "G4" at 6639.17,4467.91 h35.86
  text "Dielectric 5" at 4808.72,4396.2 h35.86
  text "FR-4 High Tg" at 5372.37,4396.2 h35.86
  text "10.31mil" at 5894.2,4396.2 h35.86
  text "3.86" at 6290.58,4396.2 h35.86
  text "6" at 4555.71,4324.49 h35.86
  text "SIG2" at 4808.72,4324.49 h35.86
  text "0.69mil" at 5894.2,4324.49 h35.86
  text "G5" at 6639.17,4324.49 h35.86
  text "Dielectric 6" at 4808.72,4252.78 h35.86
  text "FR-4 High Tg" at 5372.37,4252.78 h35.86
  text "5.00mil" at 5894.2,4252.78 h35.86
  text "3.88" at 6290.58,4252.78 h35.86
  text "7" at 4555.71,4181.07 h35.86
  text "GND2" at 4808.72,4181.07 h35.86
  text "1.26mil" at 5894.2,4181.07 h35.86
  text "G6" at 6639.17,4181.07 h35.86
  text "Dielectric 7" at 4808.72,4109.36 h35.86
  text "FR-4 High Tg" at 5372.37,4109.36 h35.86
  text "4.40mil" at 5894.2,4109.36 h35.86
  text "3.54" at 6290.58,4109.36 h35.86
  text "8" at 4555.71,4037.65 h35.86
  text "Bottom Layer" at 4808.72,4037.65 h35.86
  text "1.85mil" at 5894.2,4037.65 h35.86
  text "GBL" at 6639.17,4037.65 h35.86
  text "Bottom Solder" at 4808.72,3965.94 h35.86
  text "Solder Resist" at 5372.37,3965.94 h35.86
  text "1.00mil" at 5894.2,3965.94 h35.86
  text "3.5" at 6290.58,3965.94 h35.86
  text "GBS" at 6639.17,3965.94 h35.86
  text "Bottom Overlay" at 4808.72,3894.23 h35.86
  text "GBO" at 6639.17,3894.23 h35.86
  text "Total board thickness ():" at 4555.71,3822.52 h35.86
  text "56.53mil" at 5894.2,3822.52 h35.86
  text ".Layer_Name" at 1011.22,-901.31 h30
M13 Component Bodies Top:
  text ".Layer_Name" at 931.33,-846.68 h60
M14 Component Bodies Bottom:
  text ".Layer_Name" at 931.33,-846.68 h60
M15 Courtyards Top:
  text ".Layer_Name" at 931.33,-846.68 h60
M16 Courtyards Bottom:
  text ".Layer_Name" at 931.33,-846.68 h60
Drill Drawing:
  drawing of 154 lines, arcs and shapes, not listed
  text "Symbol" at -75.56,11629.79 h72
  text "Count" at 430.32,11629.79 h72
  text "Hole Size" at 1080.14,11629.79 h72
  text "Plated" at 2229.81,11629.79 h72
  text "Hole Type" at 2735.68,11629.79 h72
  text "Hole Tolerance (+)" at 3469.49,11629.79 h72
  text "Hole Tolerance (-)" at 4803.09,11629.79 h72
  text "Drill Layer Pair" at 6136.7,11629.79 h72
  text "Routed Path Length" at 7636.25,11629.79 h72
  text "3" at 430.32,11479.79 h60
  text "160.00mil (4.064mm)" at 1080.14,11479.79 h60
  text "PTH" at 2229.81,11479.79 h60
  text "Round" at 2735.68,11479.79 h60
  text "Top Layer - Bottom Layer" at 6136.7,11479.79 h60
  text "-" at 7636.25,11479.79 h60
  text "2" at 430.32,11329.79 h60
  text "127.95mil (3.250mm)" at 1080.14,11329.79 h60
  text "NPTH" at 2229.81,11329.79 h60
  text "Round" at 2735.68,11329.79 h60
  text "Top Layer - Bottom Layer" at 6136.7,11329.79 h60
  text "-" at 7636.25,11329.79 h60
  text "2" at 430.32,11179.79 h60
  text "98.00mil (2.489mm)" at 1080.14,11179.79 h60
  text "NPTH" at 2229.81,11179.79 h60
  text "Round" at 2735.68,11179.79 h60
  text "3.00mil (0.076mm)" at 3469.49,11179.79 h60
  text "3.00mil (0.076mm)" at 4803.09,11179.79 h60
  text "Top Layer - Bottom Layer" at 6136.7,11179.79 h60
  text "-" at 7636.25,11179.79 h60
  text "B" at -104.65,11169.8 h66.67
  text "3" at 430.32,11029.79 h60
  text "94.02mil (2.388mm)" at 1080.14,11029.79 h60
  text "PTH" at 2229.81,11029.79 h60
  text "Round" at 2735.68,11029.79 h60
  text "3.00mil (0.076mm)" at 3469.49,11029.79 h60
  text "3.00mil (0.076mm)" at 4803.09,11029.79 h60
  text "Top Layer - Bottom Layer" at 6136.7,11029.79 h60
  text "-" at 7636.25,11029.79 h60
  text "C" at -104.65,11019.8 h66.67
  text "2" at 430.32,10879.79 h60
  text "88.58mil (2.250mm)" at 1080.14,10879.79 h60
  text "NPTH" at 2229.81,10879.79 h60
  text "Round" at 2735.68,10879.79 h60
  text "Top Layer - Bottom Layer" at 6136.7,10879.79 h60
  text "-" at 7636.25,10879.79 h60
  text "E" at -104.65,10869.8 h66.67
  text "2" at 430.32,10729.79 h60
  text "66.93mil (1.700mm)" at 1080.14,10729.79 h60
  text "PTH" at 2229.81,10729.79 h60
  text "Round" at 2735.68,10729.79 h60
  text "Top Layer - Bottom Layer" at 6136.7,10729.79 h60
  text "-" at 7636.25,10729.79 h60
  text "1" at 430.32,10579.79 h60
  text "62.99mil (1.600mm)" at 1080.14,10579.79 h60
  text "NPTH" at 2229.81,10579.79 h60
  text "Round" at 2735.68,10579.79 h60
  text "3.94mil (0.100mm)" at 3469.49,10579.79 h60
  text "0.00mil (0.000mm)" at 4803.09,10579.79 h60
  text "Top Layer - Bottom Layer" at 6136.7,10579.79 h60
  text "-" at 7636.25,10579.79 h60
  text "4" at 430.32,10429.79 h60
  text "40.16mil (1.020mm)" at 1080.14,10429.79 h60
  text "NPTH" at 2229.81,10429.79 h60
  text "Round" at 2735.68,10429.79 h60
  text "Top Layer - Bottom Layer" at 6136.7,10429.79 h60
  text "-" at 7636.25,10429.79 h60
  text "4" at 430.32,10279.79 h60
  text "40.16mil (1.020mm)" at 1080.14,10279.79 h60
  text "PTH" at 2229.81,10279.79 h60
  text "Round" at 2735.68,10279.79 h60
  text "Top Layer - Bottom Layer" at 6136.7,10279.79 h60
  text "-" at 7636.25,10279.79 h60
  text "10" at 430.32,10129.79 h60
  text "40.00mil (1.016mm)" at 1080.14,10129.79 h60
  text "PTH" at 2229.81,10129.79 h60
  text "Round" at 2735.68,10129.79 h60
  text "Top Layer - Bottom Layer" at 6136.7,10129.79 h60
  text "-" at 7636.25,10129.79 h60
  text "8" at 430.32,9979.79 h60
  text "39.37mil (1.000mm)" at 1080.14,9979.79 h60
  text "PTH" at 2229.81,9979.79 h60
  text "Round" at 2735.68,9979.79 h60
  text "1.97mil (0.050mm)" at 3469.49,9979.79 h60
  text "1.97mil (0.050mm)" at 4803.09,9979.79 h60
  text "Top Layer - Bottom Layer" at 6136.7,9979.79 h60
  text "-" at 7636.25,9979.79 h60
  text "D" at -104.65,9969.8 h66.67
  text "10" at 430.32,9829.79 h60
  text "35.43mil (0.900mm)" at 1080.14,9829.79 h60
  text "PTH" at 2229.81,9829.79 h60
  text "Round" at 2735.68,9829.79 h60
  text "Top Layer - Bottom Layer" at 6136.7,9829.79 h60
  text "-" at 7636.25,9829.79 h60
  text "4" at 430.32,9679.79 h60
  text "33.47mil (0.850mm)" at 1080.14,9679.79 h60
  text "PTH" at 2229.81,9679.79 h60
  text "Round" at 2735.68,9679.79 h60
  text "Top Layer - Bottom Layer" at 6136.7,9679.79 h60
  text "-" at 7636.25,9679.79 h60
  text "26" at 430.32,9529.79 h60
  text "10.00mil (0.254mm)" at 1080.14,9529.79 h60
  text "PTH" at 2229.81,9529.79 h60
  text "Round" at 2735.68,9529.79 h60
  text "3.00mil (0.076mm)" at 3469.49,9529.79 h60
  text "3.00mil (0.076mm)" at 4803.09,9529.79 h60
  text "Top Layer - Bottom Layer" at 6136.7,9529.79 h60
  text "-" at 7636.25,9529.79 h60
  text "32" at 430.32,9379.79 h60
  text "8.00mil (0.203mm)" at 1080.14,9379.79 h60
  text "PTH" at 2229.81,9379.79 h60
  text "Round" at 2735.68,9379.79 h60
  text "Top Layer - Bottom Layer" at 6136.7,9379.79 h60
  text "-" at 7636.25,9379.79 h60
  text "1093" at 430.32,9229.79 h60
  text "8.00mil (0.203mm)" at 1080.14,9229.79 h60
  text "PTH" at 2229.81,9229.79 h60
  text "Round" at 2735.68,9229.79 h60
  text "3.00mil (0.076mm)" at 3469.49,9229.79 h60
  text "3.00mil (0.076mm)" at 4803.09,9229.79 h60
  text "Top Layer - Bottom Layer" at 6136.7,9229.79 h60
  text "-" at 7636.25,9229.79 h60
  text "A" at -104.65,9219.8 h66.67
  text "28" at 430.32,9079.79 h60
  text "7.87mil (0.200mm)" at 1080.14,9079.79 h60
  text "PTH" at 2229.81,9079.79 h60
  text "Round" at 2735.68,9079.79 h60
  text "Top Layer - Bottom Layer" at 6136.7,9079.79 h60
  text "-" at 7636.25,9079.79 h60
  text "4" at 430.32,8929.79 h60
  text "23.62mil (0.600mm)" at 1080.14,8929.79 h60
  text "PTH" at 2229.81,8929.79 h60
  text "Slot" at 2735.68,8929.79 h60
  text "Top Layer - Bottom Layer" at 6136.7,8929.79 h60
  text "27.56mil (0.700mm)" at 7636.25,8929.79 h60
  text "4" at 430.32,8779.79 h60
  text "39.37mil (1.000mm)" at 1080.14,8779.79 h60
  text "PTH" at 2229.81,8779.79 h60
  text "Rectangle" at 2735.68,8779.79 h60
  text "Top Layer - Bottom Layer" at 6136.7,8779.79 h60
  text "(Mixed)" at 7636.25,8779.79 h60
  text "1242 Total" at 430.32,8629.79 h60
  text "Slot definitions :" at -75.56,8484.82 h60
  text "Routed Path Length" at 957.13,8484.82 h60
  text "= Calculated from tool start centre position to tool end centre position." at 2059.8,8484.82 h60
  text "Hole Length" at 957.13,8384.84 h60
  text "= Routed Path Length + Tool Size = Slot length as defined in the PCB layout" at 1649.93,8384.84 h60
  text ".Layer_Name" at 469.25,-830.63 h35
DogBone Cutout:
  drawing of 459 lines, arcs and shapes, not listed
WaveGuide DXF:
  drawing of 314 lines, arcs and shapes, not listed
Top Overlay Removed:
  text ".Layer_Name" at 931.33,-846.68 h60
samtec_TOP:
  drawing of 5031 lines, arcs and shapes, not listed
  text "1.22 [30.99]" at -271.69,-932.94 h60 r90
DogBone_Cutout Gerber:
  drawing of 232 lines, arcs and shapes, not listed

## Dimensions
3346.45,0 to 3346.45,4921.25 on M2 Board Dimensions
3346.45,0 to 0,0 on M2 Board Dimensions
2749,3790 to 3826,3612.81 on M10 Fab Notes
3362.48,4921.25 to 3784.03,4920.25 on M2 Board Dimensions
3357.45,0 to 3713,-158 on M2 Board Dimensions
